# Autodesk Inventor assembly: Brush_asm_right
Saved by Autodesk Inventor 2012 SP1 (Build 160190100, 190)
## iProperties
Created: 2006-04
Part Number: Brush_asm_right
Document SubType Name: Assembly
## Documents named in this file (4)
- D:\Backup\Autodesk Motion Files\Inv2012DynSim\Sub-Assemblies\Brush_asm_right.iam
- D:\Backup\Autodesk Motion Files\Inv2012DynSim\Parts\Arm.ipt
- D:\Backup\Autodesk Motion Files\Inv2012DynSim\Parts\Wiper.ipt
- D:\Backup\Autodesk Motion Files\Inv2012DynSim\Parts\Brush.ipt
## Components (3 placed, 3 different names)
1. Arm:1
2. Wiper:1
3. Brush:1
